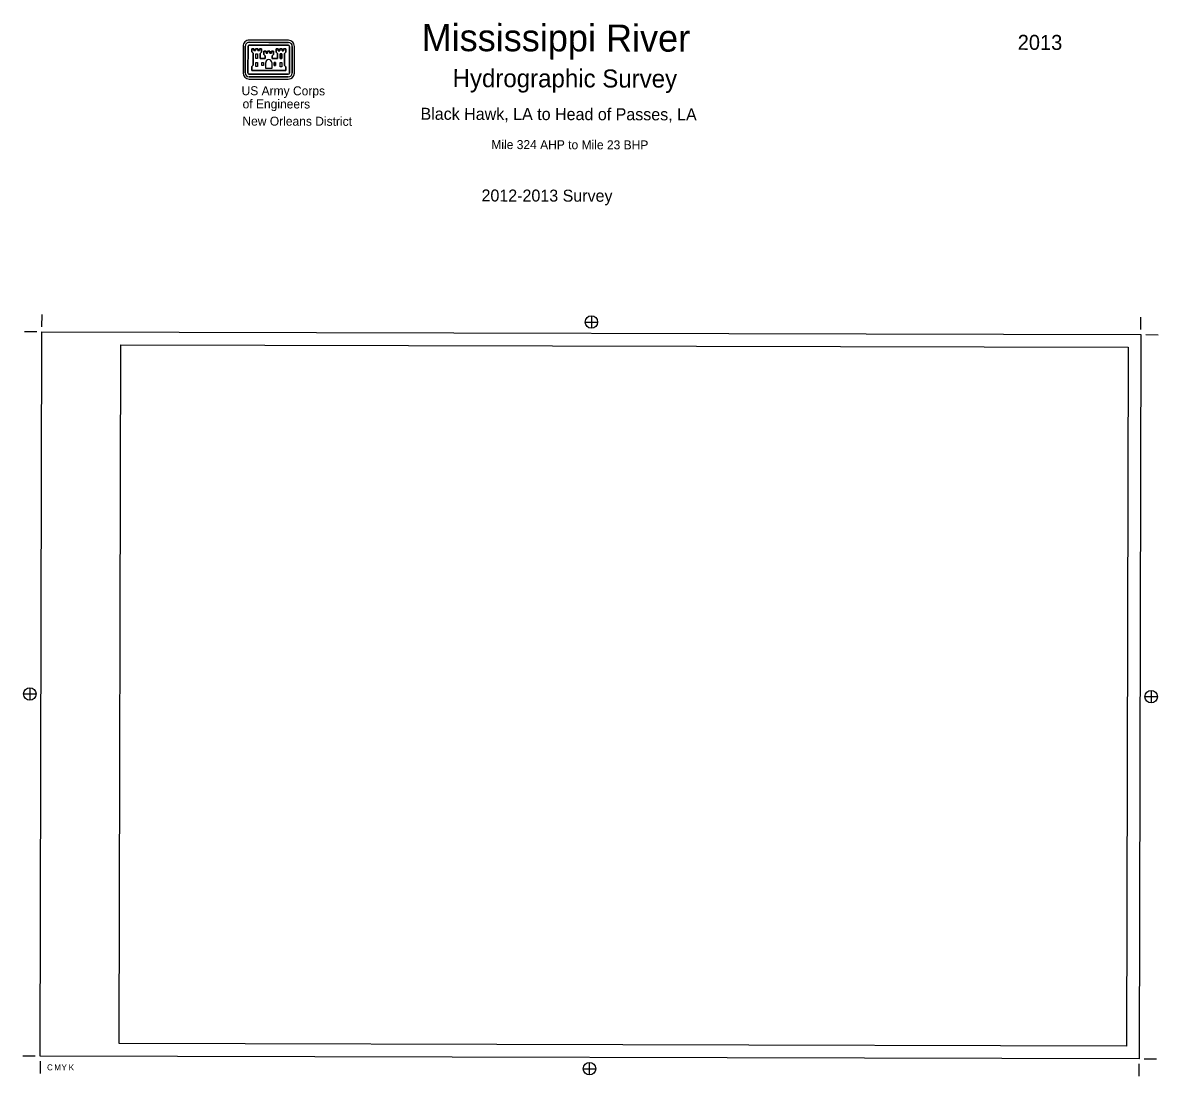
# Model space of a CAD drawing. Extents: x 3172297 to 3210190, y 958463 to 993622.
import ezdxf

# ---------------------------------------------------------------- set-up
doc = ezdxf.new("R2010")
doc.units = 0
for name, color, linetype in [('G-ANNO-NPLT', 7, 'Continuous'), ('V-ANNO-DIMS', 7, 'Continuous'), ('V-ANNO-SYMB', 7, 'Continuous'), ('V-ANNO-TEXT', 7, 'Continuous')]:
    doc.layers.add(name, color=color, linetype=linetype)

msp = doc.modelspace()

# ---------------------------------------------------------------- linework, layer by layer
at = {"layer": 'G-ANNO-NPLT'}
for points in [[(3172940, 983303), (3209606, 983213), (3209547, 959046), (3172880, 959137)], [(3172940, 983303), (3209606, 983213), (3209547, 959046), (3172880, 959137)], [(3175572, 982874), (3209188, 982791), (3209131, 959470), (3175514, 959554)]]:
    msp.add_lwpolyline(points, close=True, dxfattribs=at)
at = {"layer": 'V-ANNO-DIMS'}
for p, q in [((3172940, 983470), (3172941, 983887)), ((3191275, 983841), (3191274, 983425)), ((3209607, 983379), (3209608, 983796)), ((3191066, 983634), (3191482, 983633)), ((3172773, 983304), (3172357, 983305)), ((3209773, 983212), (3210190, 983211)), ((3172327, 971222), (3172743, 971221)), ((3172535, 971429), (3172534, 971013)), ((3209952, 971337), (3209951, 970920)), ((3210160, 971128), (3209743, 971129)), ((3172713, 959137), (3172297, 959138)), ((3172880, 958970), (3172879, 958553)), ((3191004, 958717), (3191421, 958716)), ((3191212, 958508), (3191213, 958925)), ((3209546, 958879), (3209545, 958463)), ((3209713, 959046), (3210130, 959045))]:
    msp.add_line(p, q, dxfattribs=at)
for centre in [(3191274, 983633), (3172535, 971221), (3209952, 971129), (3191212, 958716)]:
    msp.add_circle(centre, 208, dxfattribs=at)
at = {"layer": 'V-ANNO-SYMB'}
for points in [[(3179653, 992837), (3179652, 992486), (3179652, 992453), (3179650, 991946)], [(3179722, 991946), (3179723, 992483), (3179723, 992509), (3179724, 992837)], [(3179724, 992837), (3179723, 992509), (3179723, 992483), (3179722, 991946)], [(3179815, 992837), (3179812, 991946)], [(3179812, 991946), (3179815, 992837)], [(3181163, 993036), (3180509, 993037), (3179855, 993039)], [(3179855, 992967), (3180509, 992966), (3181163, 992964)], [(3181163, 992964), (3180509, 992966), (3179855, 992967)], [(3181162, 992874), (3180509, 992875), (3179855, 992877)], [(3179855, 992877), (3180509, 992875), (3181162, 992874)], [(3181200, 991942), (3181203, 992833)], [(3181203, 992833), (3181200, 991942)], [(3181293, 992833), (3181291, 991942)], [(3181291, 991942), (3181293, 992833)], [(3181362, 991942), (3181365, 992833)], [(3181074, 992153), (3181074, 992023), (3179940, 992026), (3179940, 992156), (3179985, 992201), (3179986, 992600), (3179941, 992645), (3179941, 992755), (3180013, 992755), (3180012, 992690), (3180064, 992690), (3180065, 992755), (3180142, 992755), (3180142, 992689), (3180194, 992689), (3180194, 992755), (3180265, 992754), (3180265, 992644), (3180220, 992599), (3180219, 992431), (3180391, 992430), (3180391, 992518), (3180346, 992563), (3180346, 992673), (3180417, 992673), (3180417, 992608), (3180469, 992608), (3180469, 992673), (3180547, 992673), (3180547, 992607), (3180599, 992607), (3180599, 992673), (3180670, 992672), (3180670, 992562), (3180624, 992517), (3180624, 992430), (3180796, 992429), (3180796, 992598), (3180751, 992643), (3180751, 992753), (3180823, 992753), (3180822, 992688), (3180874, 992688), (3180875, 992753), (3180952, 992753), (3180952, 992687), (3181004, 992687), (3181004, 992753), (3181075, 992752), (3181075, 992642), (3181030, 992597), (3181029, 992198), (3181074, 992153)], [(3181074, 992153), (3181029, 992198), (3181030, 992597), (3181075, 992642), (3181075, 992752), (3181004, 992753), (3181004, 992687), (3180952, 992687), (3180952, 992753), (3180875, 992753), (3180874, 992688), (3180822, 992688), (3180823, 992753), (3180751, 992753), (3180751, 992643), (3180796, 992598), (3180796, 992429), (3180624, 992430), (3180624, 992517), (3180670, 992562), (3180670, 992672), (3180599, 992673), (3180599, 992607), (3180547, 992607), (3180547, 992673), (3180469, 992673), (3180469, 992608), (3180417, 992608), (3180417, 992673), (3180346, 992673), (3180346, 992563), (3180391, 992518), (3180391, 992430), (3180219, 992431), (3180220, 992599), (3180265, 992644), (3180265, 992754), (3180194, 992755), (3180194, 992689), (3180142, 992689), (3180142, 992755), (3180065, 992755), (3180064, 992690), (3180012, 992690), (3180013, 992755), (3179941, 992755), (3179941, 992645), (3179986, 992600), (3179985, 992201), (3179940, 992156), (3179940, 992026), (3181074, 992023), (3181074, 992153)], [(3180129, 992431), (3180077, 992431), (3180077, 992580), (3180129, 992580), (3180129, 992431)], [(3180887, 992578), (3180939, 992578), (3180939, 992429), (3180887, 992429), (3180887, 992578)], [(3180128, 992155), (3180076, 992155), (3180076, 992297), (3180128, 992297), (3180128, 992155)], [(3180330, 992195), (3180279, 992195), (3180279, 992297), (3180331, 992296), (3180330, 992195)], [(3180609, 992290), (3180608, 992089), (3180507, 992090), (3180405, 992090), (3180406, 992290)], [(3180609, 992290), (3180608, 992089), (3180507, 992090), (3180405, 992090), (3180406, 992290)], [(3180735, 992194), (3180684, 992194), (3180684, 992296), (3180736, 992295), (3180735, 992194)], [(3180938, 992153), (3180886, 992153), (3180886, 992295), (3180938, 992295), (3180938, 992153)], [(3179844, 991906), (3181160, 991902)], [(3181160, 991902), (3179844, 991906)], [(3181160, 991811), (3179852, 991814)], [(3179852, 991814), (3181160, 991811)], [(3179852, 991743), (3181159, 991740)]]:
    msp.add_lwpolyline(points, dxfattribs=at)
for points in [[(3180077, 992431), (3180077, 992580), (3180129, 992580), (3180129, 992431)], [(3180887, 992578), (3180887, 992429), (3180939, 992429), (3180939, 992578)], [(3180076, 992155), (3180076, 992297), (3180128, 992297), (3180128, 992155)], [(3180279, 992195), (3180279, 992297), (3180331, 992296), (3180330, 992195)], [(3180735, 992194), (3180736, 992295), (3180684, 992296), (3180684, 992194)], [(3180886, 992153), (3180886, 992295), (3180938, 992295), (3180938, 992153)]]:
    msp.add_lwpolyline(points, close=True, dxfattribs=at)
for centre, radius, start, end in [((3179855, 992836), 202, 89.8583, 179.8583), ((3179855, 992836), 131, 89.8583, 179.8583), ((3179855, 992836), 131, 89.8583, 179.8583), ((3179855, 992836), 40.4, 89.8583, 179.8583), ((3179855, 992836), 40.4, 89.8583, 179.8583), ((3181162, 992833), 40.4, 359.8583, 89.8583), ((3181162, 992833), 40.4, 359.8583, 89.8583), ((3181162, 992833), 202, 359.8583, 89.8583), ((3181162, 992833), 131, 359.8583, 89.8583), ((3181162, 992833), 131, 359.8583, 89.8583), ((3180507, 992290), 101, 89.838, 179.838), ((3180507, 992290), 101, 89.838, 179.838), ((3180507, 992290), 101, 359.9092, 89.9092), ((3180507, 992290), 101, 359.9092, 89.9092), ((3179853, 991945), 203, 179.83, 269.83), ((3179853, 991945), 131, 179.8583, 269.8583), ((3179853, 991945), 131, 179.8583, 269.8583), ((3179853, 991945), 40.5, 179.7169, 257.166), ((3179853, 991945), 40.5, 179.7169, 257.166), ((3181160, 991942), 203, 269.8866, 359.8866), ((3181160, 991942), 131, 269.8583, 359.8583), ((3181160, 991942), 40.5, 269.9998, 359.9998), ((3181160, 991942), 131, 269.8583, 359.8583), ((3181160, 991942), 40.5, 269.9998, 359.9998)]:
    msp.add_arc(centre, radius, start, end, dxfattribs=at)

# ---------------------------------------------------------------- texts
at = {"layer": 'V-ANNO-DIMS'}
for s, p in [('C', (3173108, 958662)), ('M', (3173350, 958661)), ('Y', (3173591, 958660)), ('K', (3173833, 958660))]:
    msp.add_text(s, height=199, rotation=359.8583, dxfattribs=at).set_placement(p)
at = {"layer": 'V-ANNO-TEXT'}
for s, height, p in [('Mississippi River', 900, (3185607, 992676)), ('2013', 500, (3205498, 992717)), ('Hydrographic Survey', 600, (3186641, 991473)), ('US Army Corps', 300, (3179599, 991203)), ('of Engineers', 300, (3179633, 990764)), ('Black Hawk, LA to Head of Passes, LA', 400, (3185571, 990383)), ('New Orleans District', 300, (3179628, 990189)), ('Mile 324 AHP to Mile 23 BHP', 300, (3187934, 989406)), ('2012-2013 Survey', 400, (3187606, 987657))]:
    msp.add_text(s, height=height, rotation=359.8583, dxfattribs=at).set_placement(p)

doc.saveas('drawing.dxf')
